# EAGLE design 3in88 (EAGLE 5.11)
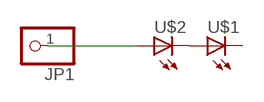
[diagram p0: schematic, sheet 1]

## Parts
JP1  PINHD-1X11X0.4  [1X01]
U$1  LEDSMT1206  [1206]
U$2  LEDSMT1206  [1206]

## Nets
N$1: JP1.1 U$2.A
N$3: U$1.A U$2.C
Unconnected: U$1.C

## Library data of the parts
JP1 = pinhead:PINHD-1X1: PIN HEADER
U$1 U$2 = led(2):LED: LED

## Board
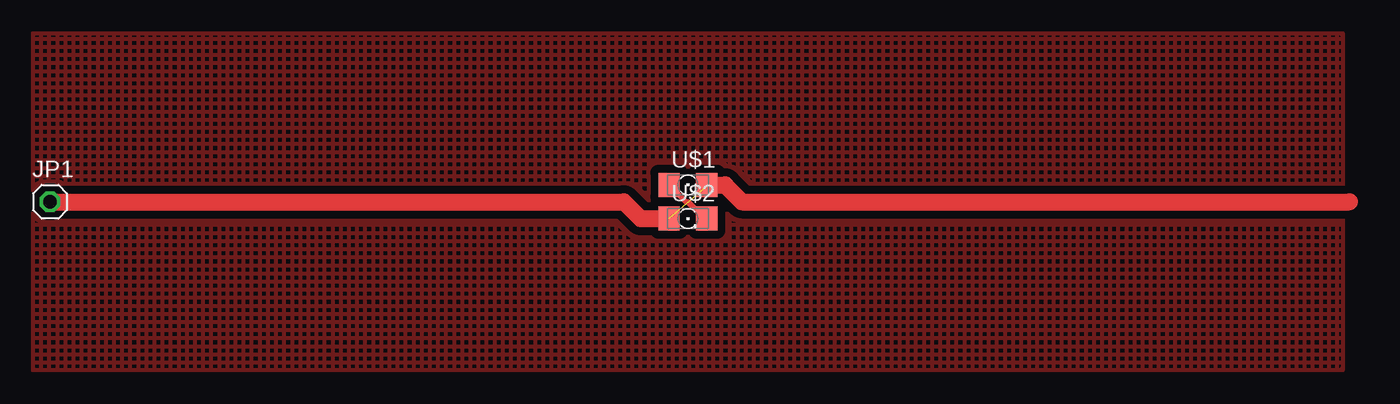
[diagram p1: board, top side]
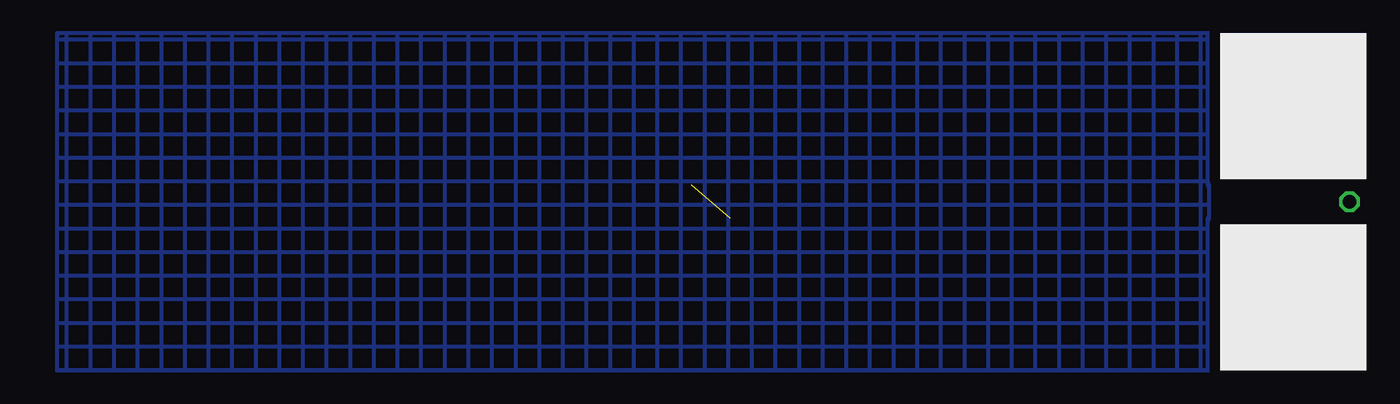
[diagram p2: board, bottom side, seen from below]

No outline drawn. Coordinates in mm, seen from the top.
Copper layers (1*16): Top 0.035mm / dielectric 1.5mm / Bottom 0.035mm
Design rules "default": minimum track width 10mil, minimum drill 24mil, track to track 8mil, track to pad 8mil, pad to pad 8mil, via to via 8mil, smd to smd 8mil, copper to edge 40mil, drill to drill 8mil, minimum pad ring 10mil, minimum via ring 8mil, stop-mask expansion 4mil, vias tented up to drill 0mil, thermal gap 10mil

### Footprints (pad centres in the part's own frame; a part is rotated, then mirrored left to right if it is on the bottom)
1X01 = drill 1.016 octagon: 1 0,0
1206 = smd 1.6 x 1.803: A -1.422,0; C 1.422,0

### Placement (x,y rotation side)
JP1  1.27,12.7 0 top
U$1  49.28,13.97 0 top
U$2  49.28,11.43 0 top
U$3  [SMD11]  5.5,19.9 0 bottom
U$5  [SMD11]  5.5,5.5 0 bottom

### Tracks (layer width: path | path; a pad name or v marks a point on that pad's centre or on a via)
N$1  (1 unrouted)
  Top 1.27: JP1.1 44.45,12.7 45.72,11.43 U$2.A | 99.06,12.7 53.34,12.7 52.07,13.97 50.8,13.97
N$2
  pour Top (isolate 0.61, hatched): 0,25.4 98.55,25.4 98.55,0 0,0
  pour Bottom (isolate 0.813, hatched): 11.81,25.4 98.55,25.4 98.55,0 11.81,0
N$3
  Top 0.406: U$1.A 47.88,13.97 49.15,12.7 49.28,12.7 50.04,11.94 50.19,11.94 U$2.C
